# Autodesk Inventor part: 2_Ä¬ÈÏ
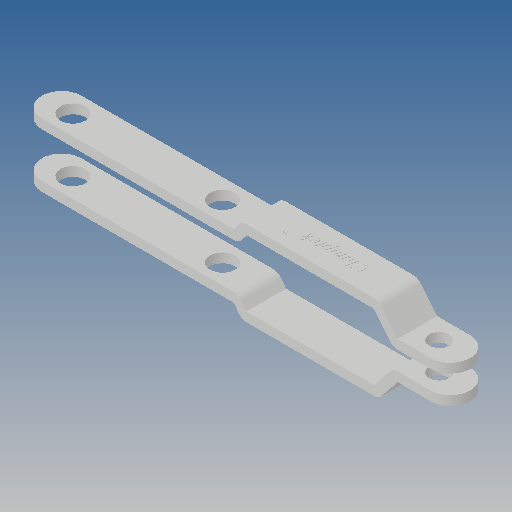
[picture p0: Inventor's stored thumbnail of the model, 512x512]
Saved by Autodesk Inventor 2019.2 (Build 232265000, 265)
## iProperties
Created: 2010-06
Part Number: 2_Ä¬ÈÏ
Material: Ogólny
Document SubType Name: Modeling
Designer: CADENGINEERING4
Density: 1 g/cm^3
Appearance: Domyślna
Author: CADENGINEERING4
Revision Number: ÈÎºÎ
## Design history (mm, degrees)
feature "NONE"
feature "NONE:1"
node "Bryła1"
node "Bryła2"
